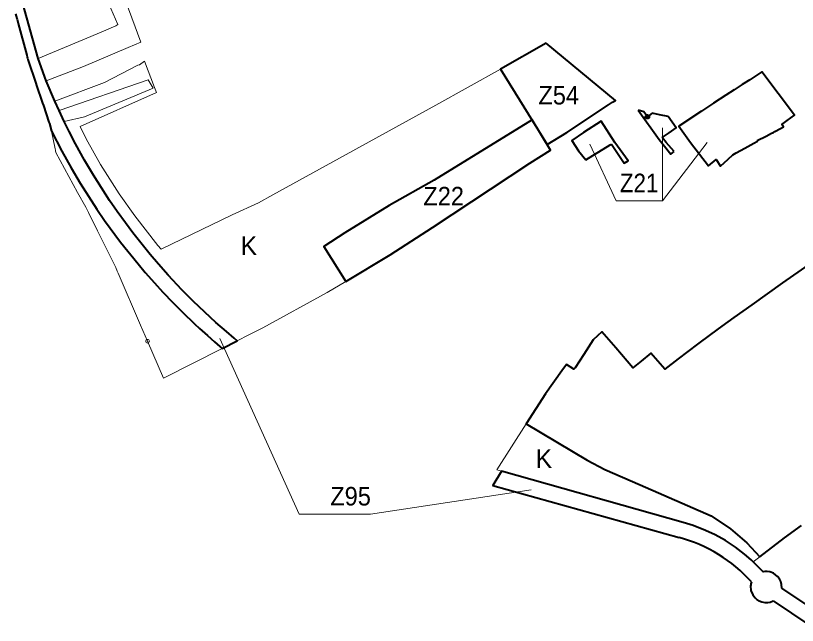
# Model space of a CAD drawing. Extents: x -650276 to -642489, y -1074311 to -1066658.
# Drawn here: x -649054 to -648043, y -1071488 to -1070699 of the extents above; entities that cross this region are included whole.
import ezdxf

# ---------------------------------------------------------------- set-up
doc = ezdxf.new("R2010")
doc.units = 0
doc.header["$LTSCALE"] = 9.6
doc.header["$PDMODE"] = 32
doc.header["$PDSIZE"] = 4.8
for name, color, linetype, lineweight in [('2', 7, 'Continuous', 40), ('42', 7, 'Continuous', 25), ('44', 7, 'Continuous', 40), ('45', 7, 'Continuous', 40), ('46', 7, 'Continuous', 13), ('47', 7, 'Continuous', 13), ('48', 7, 'Continuous', 35)]:
    doc.layers.add(name, color=color, linetype=linetype, lineweight=lineweight)

msp = doc.modelspace()

# ---------------------------------------------------------------- linework, layer by layer
at = {"layer": '2', "lineweight": 13}
msp.add_line((-648217.945, -1070938.322), (-648217.945, -1070843.952), dxfattribs=at)
at = {"layer": '2'}
msp.add_lwpolyline([(-648368.163, -1070734.376), (-648427.25, -1070767.95), (-648366.98, -1070865.44), (-648341.58, -1070849.98), (-648287.74, -1070814.32), (-648282.44, -1070810.84), (-648278.832, -1070808.761)], close=True, dxfattribs=at)
for points in [[(-648237.46, -1070829.68), (-648241.96, -1070823.46), (-648249.5, -1070821.08)], [(-648249.5, -1070821.08), (-648222.158, -1070859.221), (-648217.1, -1070865.56), (-648207.151, -1070878.029), (-648202.798, -1070874.754)], [(-648210.517, -1070829.445), (-648221.58, -1070827.03), (-648231.22, -1070824.92), (-648237.46, -1070829.68)], [(-648284.02, -1070864.91), (-648267.24, -1070889.9), (-648262.4, -1070886.58), (-648279.39, -1070862.98), (-648297.39, -1070835.36), (-648320.02, -1070850.16), (-648335.19, -1070860.49), (-648326.41, -1070873.55), (-648317.14, -1070885.48)], [(-648218.11, -1070856.44), (-648209.37, -1070850.44), (-648200.17, -1070844.094), (-648210.517, -1070829.445)], [(-648202.798, -1070874.754), (-648212.94, -1070862.74), (-648217.85, -1070856.93), (-648218.11, -1070856.44)], [(-648317.14, -1070885.48), (-648285.72, -1070865.96), (-648284.02, -1070864.91)]]:
    msp.add_lwpolyline(points, dxfattribs=at)
at = {"layer": '2', "lineweight": 13}
msp.add_lwpolyline([(-648217.945, -1070938.322), (-648277.841, -1070938.322), (-648311.985, -1070865.23)], dxfattribs=at)
at = {"layer": '2'}
msp.add_point((-648237.46, -1070829.68), dxfattribs=at)
at = {"layer": '42'}
msp.add_lwpolyline([(-648386.587, -1070833.807), (-648512.981, -1070911.776), (-648571.14, -1070944.67), (-648628.712, -1070979.892), (-648655.76, -1070997.5), (-648627.39, -1071042.65), (-648570.23, -1071008.2), (-648515.46, -1070972.94), (-648389.33, -1070889.79), (-648362.519, -1070872.788)], close=True, dxfattribs=at)
at = {"layer": '44'}
for points in [[(-649054.31, -1070696.44), (-649052.77, -1070702.25), (-649052.44, -1070703.48), (-649051.03, -1070708.74), (-649040.03, -1070750.06), (-649039.38, -1070752.51), (-649039.06, -1070753.72), (-649038.51, -1070755.38), (-649027.74, -1070787.51), (-649027.64, -1070787.8), (-649019.48, -1070812.18), (-649018.48, -1070815.18), (-649011.24, -1070836.79), (-649010.67, -1070838.5), (-649007.885, -1070848.153), (-648994.464, -1070873.974), (-648982.467, -1070895.704), (-648970.712, -1070915.663), (-648960.268, -1070932.429), (-648949.389, -1070949.031), (-648939.232, -1070963.818), (-648918.601, -1070991.969), (-648896.068, -1071020.184), (-648886.874, -1071031.044), (-648874.793, -1071044.773), (-648863.847, -1071056.723), (-648851.175, -1071069.886), (-648838.696, -1071082.562), (-648823.087, -1071097.562), (-648816.379, -1071103.782), (-648806.239, -1071112.938), (-648797, -1071121), (-648790.23, -1071126.818), (-648787.207, -1071129.363), (-648767.824, -1071119.455), (-648771.725, -1071116.233), (-648781.806, -1071107.721), (-648795.407, -1071095.8), (-648824.292, -1071068.677), (-648839.273, -1071053.556), (-648856.883, -1071034.761), (-648869.629, -1071020.411), (-648880.44, -1071007.703), (-648894.164, -1070990.806), (-648902.714, -1070979.812), (-648912.396, -1070966.893), (-648922.92, -1070952.242), (-648932.78, -1070937.887), (-648943.414, -1070921.659), (-648953.605, -1070905.299), (-648965.093, -1070885.794), (-648976.834, -1070864.527), (-648985.145, -1070848.538), (-648991.386, -1070835.954), (-648998.132, -1070821.723), (-649003.641, -1070809.566), (-649014.888, -1070782.994), (-649025.129, -1070754.377), (-649047.11, -1070674.743)], [(-648079.109, -1071418.563), (-648082.391, -1071418.063), (-648085.477, -1071418.086), (-648087.928, -1071418.446), (-648100.438, -1071405.517), (-648103.268, -1071402.88), (-648111.646, -1071395.618), (-648123.313, -1071386.696), (-648136.263, -1071378.194), (-648149.571, -1071370.788), (-648162.084, -1071364.918), (-648178.158, -1071358.781), (-648191.25, -1071354.858), (-648426.18, -1071288.32), (-648437.454, -1071306.778), (-648196.236, -1071374.226)], [(-648069.022, -1071424.443), (-648074.341, -1071420.189), (-648079.108, -1071418.564), (-648079.109, -1071418.563)], [(-648063.593, -1071439.723), (-648063.862, -1071435.078), (-648064.838, -1071431.28), (-648066.623, -1071427.592), (-648069.022, -1071424.443)], [(-648103.894, -1071436.836), (-648103.478, -1071442.736), (-648101.203, -1071448.31)], [(-648016.446, -1071471.268), (-648063.593, -1071439.723)], [(-648101.203, -1071448.31), (-648098.259, -1071452.196), (-648096.014, -1071454.192), (-648093.059, -1071456.066), (-648089.539, -1071457.489), (-648085.585, -1071458.248), (-648081.642, -1071458.215), (-648078.539, -1071457.636), (-648074.86, -1071456.248)], [(-648074.86, -1071456.248), (-648027.562, -1071487.894)]]:
    msp.add_lwpolyline(points, dxfattribs=at)
at = {"layer": '44', "lineweight": 13}
msp.add_lwpolyline([(-648790.074, -1071116.496), (-648687.825, -1071343.817), (-648595.588, -1071343.817), (-648387.63, -1071312.498)], dxfattribs=at)
at = {"layer": '44'}
for centre, radius, start, end in [((-648244.965, -1071557.871), 190, 41.59858, 75.1393), ((-648083.781, -1071438.172), 20.157, 161.35794, 176.20098)]:
    msp.add_arc(centre, radius, start, end, dxfattribs=at)
at = {"layer": '45'}
for points in [[(-648095.42, -1070860.3), (-648083.65, -1070854.89), (-648076.73, -1070851.07), (-648074.41, -1070849.79), (-648072.59, -1070848.79), (-648065.35, -1070844.8), (-648061.52, -1070842.68), (-648063.76, -1070839.49), (-648056.61, -1070834.26), (-648047.17, -1070827.35), (-648089.27, -1070771.57), (-648104.78, -1070781.65), (-648114.77, -1070788.08), (-648125.2, -1070794.79), (-648136.08, -1070801.79)], [(-648095.42, -1070860.3), (-648083.65, -1070854.89), (-648076.73, -1070851.07), (-648074.41, -1070849.79), (-648072.59, -1070848.79), (-648065.35, -1070844.8), (-648061.52, -1070842.68), (-648063.76, -1070839.49), (-648056.61, -1070834.26), (-648047.17, -1070827.35), (-648089.27, -1070771.57), (-648104.78, -1070781.65), (-648114.77, -1070788.08), (-648125.2, -1070794.79), (-648136.08, -1070801.79)], [(-648136.08, -1070801.79), (-648151.77, -1070812.11), (-648167.6, -1070822.53), (-648196.65, -1070841.7), (-648181.75, -1070862.74), (-648158.58, -1070892.98), (-648148.34, -1070884.92), (-648142.79, -1070893.78), (-648133.14, -1070884.6), (-648127, -1070878.75), (-648122.72, -1070876.44), (-648111.24, -1070870.11), (-648099.85, -1070863.82), (-648094.9, -1070861.09), (-648095.42, -1070860.3)], [(-648136.08, -1070801.79), (-648151.77, -1070812.11), (-648167.6, -1070822.53), (-648196.65, -1070841.7), (-648181.75, -1070862.74), (-648158.58, -1070892.98), (-648148.34, -1070884.92), (-648142.79, -1070893.78), (-648133.14, -1070884.6), (-648127, -1070878.75), (-648122.72, -1070876.44), (-648111.24, -1070870.11), (-648099.85, -1070863.82), (-648094.9, -1070861.09), (-648095.42, -1070860.3)], [(-648386.587, -1070833.807), (-648512.981, -1070911.776), (-648571.14, -1070944.67), (-648628.712, -1070979.892), (-648655.76, -1070997.5), (-648627.39, -1071042.65), (-648570.23, -1071008.2), (-648515.46, -1070972.94), (-648389.33, -1070889.79)], [(-648386.587, -1070833.807), (-648512.981, -1070911.776), (-648571.14, -1070944.67), (-648628.712, -1070979.892), (-648655.76, -1070997.5), (-648627.39, -1071042.65), (-648570.23, -1071008.2), (-648515.46, -1070972.94), (-648389.33, -1070889.79)], [(-648389.33, -1070889.79), (-648362.519, -1070872.788), (-648386.587, -1070833.807)], [(-648389.33, -1070889.79), (-648362.519, -1070872.788), (-648386.587, -1070833.807)], [(-647913.45, -1070940.79), (-648062.53, -1071044.59), (-648102.55, -1071072.86), (-648125.53, -1071089.51), (-648141.12, -1071100.71), (-648155.77, -1071111.23), (-648172.48, -1071123.95), (-648197.57, -1071143.03), (-648215.08, -1071156.35), (-648232.8, -1071135.6), (-648245.49, -1071145.91), (-648256.04, -1071154.5), (-648278.39, -1071128.74), (-648296.34, -1071108.04), (-648307.33, -1071118.47), (-648319.77, -1071137.52), (-648330.78, -1071154.36), (-648332.354, -1071156.279), (-648341.943, -1071150.071), (-648347.949, -1071158.385), (-648369.33, -1071188.149), (-648394.087, -1071227.18), (-648315.127, -1071274.052), (-648292.406, -1071286.112), (-648246.752, -1071306.054), (-648155.113, -1071346.082), (-648130, -1071363), (-648109, -1071381), (-648091.92, -1071399.07), (-648060.01, -1071374.69), (-648038.18, -1071358.51)]]:
    msp.add_lwpolyline(points, dxfattribs=at)
at = {"layer": '46'}
for points in [[(-648277.841, -1070938.322), (-648217.945, -1070938.322), (-648160.135, -1070863.066)], [(-648217.945, -1070938.322), (-648217.945, -1070938.322), (-648160.135, -1070863.066)]]:
    msp.add_lwpolyline(points, dxfattribs=at)
at = {"layer": '47'}
for p, q in [((-648883.73, -1071120.13), (-648862.97, -1071168.09)), ((-648862.97, -1071168.09), (-648787.207, -1071129.363)), ((-648191.25, -1071354.858), (-648178.158, -1071358.781))]:
    msp.add_line(p, q, dxfattribs=at)
msp.add_lwpolyline([(-649014.888, -1070782.994), (-648966.35, -1070764.7), (-648908.94, -1070740.19), (-648892.215, -1070733.293), (-648927.2, -1070637.98), (-648941.064, -1070599.735), (-648965.569, -1070610.382), (-648956.687, -1070630.825), (-649050.081, -1070663.981), (-649047.11, -1070674.743), (-648952.455, -1070640.564), (-648922.196, -1070710.207), (-648924.668, -1070712.022), (-648943.837, -1070720.104), (-649025.129, -1070754.377)], close=True, dxfattribs=at)
for points in [[(-648971.041, -1070842.231), (-648872.375, -1070798.112), (-648874.87, -1070791.61), (-648887.84, -1070757.84), (-648894.08, -1070762.22), (-648896.11, -1070762.73), (-648939.5, -1070785.4), (-649003.641, -1070809.566), (-648998.132, -1070821.723), (-648882.919, -1070781.673), (-648876.64, -1070792.6), (-648965.475, -1070829.829), (-648991.386, -1070835.954)], [(-648386.587, -1070833.807), (-648427.25, -1070767.95), (-648511.09, -1070814.7), (-648721.54, -1070930.88), (-648740.25, -1070941.21), (-648774.23, -1070956.42), (-648866.341, -1071000.881)], [(-648991.386, -1070835.954), (-648985.145, -1070848.538), (-648976.834, -1070864.527), (-648965.093, -1070885.794), (-648953.605, -1070905.299), (-648943.414, -1070921.659), (-648932.78, -1070937.887), (-648922.92, -1070952.242), (-648912.396, -1070966.893), (-648902.714, -1070979.812), (-648894.164, -1070990.806), (-648880.44, -1071007.703), (-648869.629, -1071020.411), (-648856.883, -1071034.761), (-648839.273, -1071053.556), (-648824.292, -1071068.677)], [(-648571.14, -1070944.67), (-648512.981, -1070911.776), (-648386.587, -1070833.807)], [(-648866.341, -1071000.881), (-648870.479, -1070996.265), (-648900.337, -1070957.964), (-648920.293, -1070929.567), (-648944.376, -1070891.404), (-648963.107, -1070858.328), (-648971.041, -1070842.231)], [(-648787.207, -1071129.363), (-648790.23, -1071126.818), (-648797, -1071121), (-648806.239, -1071112.938), (-648816.379, -1071103.782), (-648823.087, -1071097.562), (-648838.696, -1071082.562), (-648851.175, -1071069.886), (-648863.847, -1071056.723), (-648874.793, -1071044.773), (-648886.874, -1071031.044), (-648896.068, -1071020.184), (-648918.601, -1070991.969), (-648939.232, -1070963.818), (-648949.389, -1070949.031), (-648960.268, -1070932.429), (-648970.712, -1070915.663), (-648982.467, -1070895.704), (-648994.464, -1070873.974), (-649007.885, -1070848.153), (-649003.1, -1070871.35), (-649002.82, -1070872.69), (-649002.62, -1070873.69), (-649002.15, -1070875.96), (-648974.4, -1070927.77), (-648963.5, -1070946.45), (-648959.92, -1070953.73), (-648948.29, -1070977.37), (-648924.92, -1071024.89), (-648922.98, -1071029.49), (-648921.87, -1071032.04), (-648892.82, -1071099.15), (-648883.73, -1071120.13)], [(-648752.967, -1071111.861), (-648734.849, -1071102.599), (-648651.375, -1071057.109), (-648627.39, -1071042.65), (-648655.76, -1070997.5), (-648634.07, -1070983.17), (-648628.712, -1070979.892), (-648571.153, -1070944.678), (-648571.14, -1070944.67)], [(-648824.292, -1071068.677), (-648795.407, -1071095.8), (-648781.806, -1071107.721), (-648771.725, -1071116.233), (-648767.824, -1071119.455), (-648752.967, -1071111.861)], [(-648130, -1071363), (-648155.113, -1071346.082), (-648246.752, -1071306.054), (-648292.406, -1071286.112), (-648315.127, -1071274.052), (-648394.104, -1071227.17), (-648432.093, -1071286.645), (-648426.18, -1071288.32), (-648191.25, -1071354.858)], [(-648178.158, -1071358.781), (-648178.158, -1071358.781), (-648162.084, -1071364.918)], [(-648162.084, -1071364.918), (-648149.571, -1071370.788), (-648136.263, -1071378.194)], [(-648136.263, -1071378.194), (-648136.263, -1071378.194), (-648123.313, -1071386.696), (-648111.646, -1071395.618), (-648103.268, -1071402.88), (-648100.438, -1071405.517), (-648091.92, -1071399.07), (-648109, -1071381), (-648130, -1071363)]]:
    msp.add_lwpolyline(points, dxfattribs=at)
msp.add_point((-648883.73, -1071120.13), dxfattribs=at)

# ---------------------------------------------------------------- texts
at = {"layer": '2'}
for s, width, p in [('Z54', 0.95, (-648378.37, -1070813.706)), ('Z21', 0.9, (-648272.998, -1070927.282))]:
    msp.add_text(s, height=24, dxfattribs=dict(at, width=width)).set_placement(p)
at = {"layer": '44', "width": 0.95}
msp.add_text('Z95', height=24, dxfattribs=at).set_placement((-648647.497, -1071332.741))
at = {"layer": '46', "width": 0.95}
msp.add_text('Z22', height=24, dxfattribs=at).set_placement((-648527.125, -1070944.357))
msp.add_text('Z22', height=24, dxfattribs=at).set_placement((-648527.125, -1070944.357))
at = {"layer": '48'}
for p in [(-648763.558, -1071008.525), (-648763.558, -1071008.525), (-648382.039, -1071284.028)]:
    msp.add_text('K', height=24, dxfattribs=at).set_placement(p)

doc.saveas('drawing.dxf')
